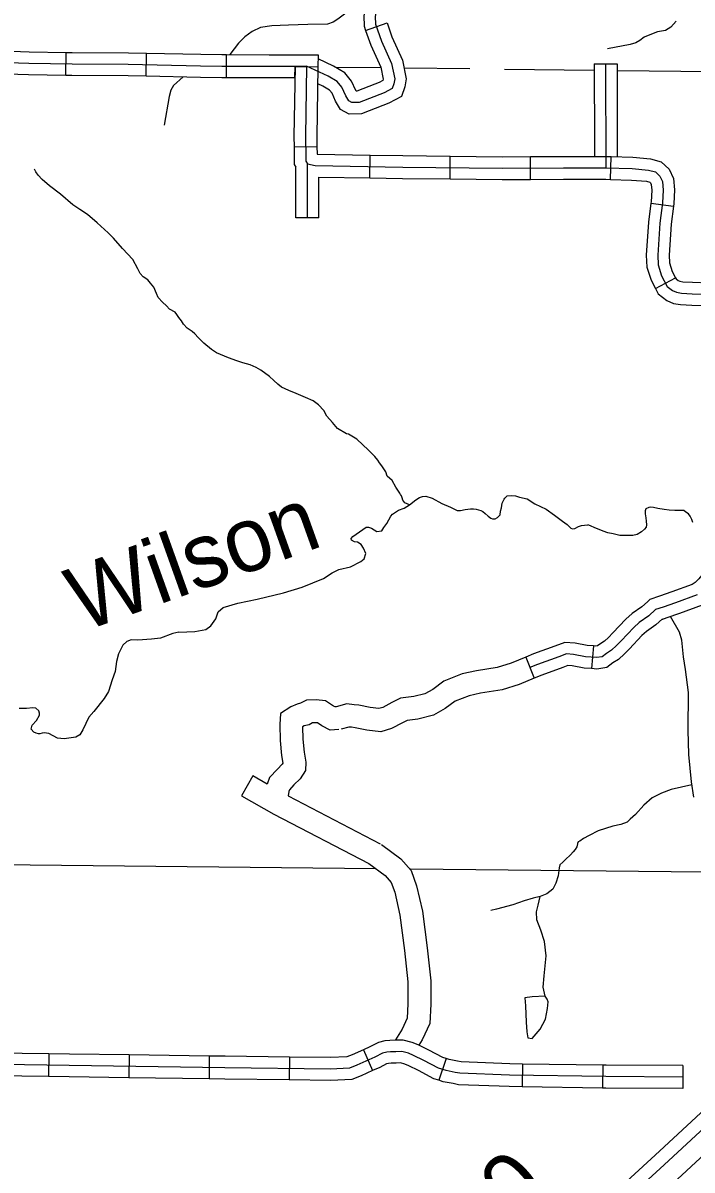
# Model space of a CAD drawing. Extents: x 8749 to 11879, y 13275 to 15339.
# Drawn here: x 9903.6 to 9991.7, y 13618.1 to 13768.9 of the extents above; entities that cross this region are included whole.
import ezdxf

# ---------------------------------------------------------------- set-up
doc = ezdxf.new("R2010")
doc.units = 0
for name, color, linetype in [('Level 19', 7, 'Continuous'), ('Level 31', 7, 'Continuous'), ('Level 32', 7, 'Continuous'), ('Level 35', 7, 'Continuous'), ('Level 45', 7, 'Continuous'), ('Level 46', 7, 'Continuous'), ('Level 48', 7, 'Continuous'), ('Level 5', 7, 'Continuous')]:
    doc.layers.add(name, color=color, linetype=linetype)

msp = doc.modelspace()

# ---------------------------------------------------------------- linework, layer by layer
at = {"layer": 'Level 19'}
for points in [[(9996.99, 13629.44), (9986.85, 13620.03), (9964.99, 13600.02), (9954.18, 13590.48), (9938.87, 13577.88), (9926.88, 13568.51), (9905.66, 13552.12), (9898.16, 13546.32), (9886.51, 13537.43), (9886.51, 13535.29)], [(9886.51, 13535.29), (9899.2, 13544.97), (9906.7, 13550.77), (9927.92, 13567.17), (9939.93, 13576.55), (9955.28, 13589.19), (9966.13, 13598.75), (9988, 13618.78), (9998.09, 13628.1)], [(9999.89, 13626.27), (9989.76, 13616.86), (9967.87, 13596.82), (9956.97, 13587.21), (9941.56, 13574.52), (9929.52, 13565.11), (9908.29, 13548.72), (9900.79, 13542.91), (9886.98, 13532.37)]]:
    msp.add_lwpolyline(points, dxfattribs=at)
at = {"layer": 'Level 31'}
for points in [[(9888.21, 13763.88), (9897.6, 13763.86), (9904.42, 13763.63), (9910.12, 13763.54), (9917.5, 13763.5), (9927.02, 13763.29), (9929.81, 13763.25), (9936.03, 13763.23), (9939.44, 13763.23), (9940.96, 13763.23)], [(9940.96, 13763.23), (9940.81, 13753.97), (9940.85, 13751.33), (9940.85, 13750.74), (9941.07, 13750.41), (9942.09, 13750.16), (9953.63, 13749.97), (9966.7, 13749.83), (9974.76, 13749.86), (9980.36, 13749.86)], [(9980.36, 13749.86), (9983.8, 13749.76), (9985.96, 13749.57), (9986.87, 13749.32), (9987.46, 13748.77), (9987.79, 13748.07), (9987.9, 13746.93), (9987.79, 13745.25), (9987.46, 13742.59), (9987.17, 13738.37), (9987.24, 13737.09), (9987.68, 13735.66), (9988.41, 13734.27), (9989.11, 13733.72), (9989.66, 13733.5), (9990.32, 13733.39), (9991.71, 13733.31), (9993.79, 13733.24), (9996.32, 13733.06), (9998.74, 13732.91), (10002.14, 13732.4), (10004.11, 13732.12)], [(9992.36, 13693.72), (9989.51, 13692.68), (9987.89, 13692.1), (9986.9, 13691.77), (9985.99, 13690.97), (9984.74, 13690.09), (9984.01, 13689.43), (9982.36, 13687.67), (9981.74, 13687.04), (9981.08, 13686.42), (9980.42, 13686.02), (9979.87, 13685.58), (9979.1, 13685.47), (9977.67, 13685.58), (9976.1, 13685.87), (9975.15, 13685.94), (9974.16, 13685.58), (9971.37, 13684.55), (9970.35, 13684.15)]]:
    msp.add_lwpolyline(points, dxfattribs=at)
at = {"layer": 'Level 32'}
for p, q in [((9909.3, 13762.06), (9909.35, 13765.05)), ((9919.85, 13761.95), (9919.92, 13764.95)), ((9930.44, 13761.75), (9930.45, 13764.75)), ((9939.46, 13763.21), (9942.46, 13763.16)), ((9939.33, 13752.61), (9942.33, 13752.65)), ((9949.29, 13748.54), (9949.33, 13751.54)), ((9959.85, 13748.4), (9959.88, 13751.4)), ((9970.43, 13748.34), (9970.42, 13751.34)), ((9980.94, 13748.34), (9981.03, 13751.34)), ((9986.27, 13745.21), (9989.25, 13744.84)), ((9942.57, 13743.3), (9939.57, 13743.3)), ((9986.86, 13733.99), (9989.52, 13735.39)), ((9907.06, 13633.36), (9907.01, 13630.36)), ((9917.61, 13633.21), (9917.57, 13630.21)), ((9928.17, 13633.07), (9928.13, 13630.07)), ((9938.73, 13632.93), (9938.69, 13629.93)), ((9948.44, 13633.89), (9949.66, 13631.15)), ((9959.32, 13632.73), (9958.39, 13629.88)), ((9969.38, 13632.02), (9969.33, 13629.02)), ((9979.93, 13631.86), (9979.89, 13628.86)), ((9990.48, 13631.81), (9990.46, 13628.81))]:
    msp.add_line(p, q, dxfattribs=at)
for points in [[(9898.82, 13765.32), (9904.46, 13765.13), (9909.35, 13765.05)], [(9909.35, 13765.05), (9910.13, 13765.04), (9917.52, 13765), (9919.92, 13764.95)], [(9919.92, 13764.95), (9927.05, 13764.79), (9929.83, 13764.75), (9930.45, 13764.75)], [(9930.45, 13764.75), (9936.03, 13764.73), (9939.44, 13764.73), (9942.49, 13764.73), (9942.46, 13763.16)], [(9898.72, 13762.32), (9904.39, 13762.13), (9909.3, 13762.06)], [(9930.44, 13761.75), (9936.02, 13761.73), (9939.44, 13761.73), (9939.44, 13761.73), (9939.46, 13763.22)], [(9939.46, 13763.21), (9939.31, 13753.97), (9939.33, 13752.61)], [(9942.46, 13763.16), (9942.31, 13753.97), (9942.33, 13752.65)], [(9909.3, 13762.06), (9910.1, 13762.04), (9917.48, 13762), (9919.85, 13761.95)], [(9919.85, 13761.95), (9926.99, 13761.79), (9929.8, 13761.75), (9930.44, 13761.75)], [(9939.33, 13752.61), (9939.35, 13751.32), (9939.35, 13750.29), (9939.57, 13749.96)], [(9942.33, 13752.65), (9942.34, 13751.65), (9949.33, 13751.54)], [(9941.07, 13743.3), (9941.07, 13750.41)], [(9949.33, 13751.54), (9953.65, 13751.47), (9959.88, 13751.4)], [(9959.88, 13751.4), (9966.7, 13751.33), (9970.42, 13751.34)], [(9970.42, 13751.34), (9974.75, 13751.36), (9980.38, 13751.36), (9981.03, 13751.34)], [(9981.03, 13751.34), (9983.88, 13751.26), (9986.23, 13751.06), (9987.63, 13750.66), (9988.69, 13749.67), (9989.26, 13748.48), (9989.4, 13746.96), (9989.28, 13745.11), (9989.25, 13744.84)], [(9939.57, 13743.3), (9939.57, 13749.96)], [(9942.57, 13743.3), (9942.57, 13748.65)], [(9942.57, 13748.65), (9949.29, 13748.54)], [(9949.29, 13748.54), (9953.61, 13748.47), (9959.85, 13748.4)], [(9959.85, 13748.4), (9966.69, 13748.33), (9970.43, 13748.34)], [(9970.43, 13748.34), (9974.76, 13748.36), (9980.34, 13748.36), (9980.94, 13748.34)], [(9980.94, 13748.34), (9983.71, 13748.26), (9985.69, 13748.09), (9986.12, 13747.97), (9986.23, 13747.87), (9986.32, 13747.67), (9986.39, 13746.91), (9986.3, 13745.39), (9986.27, 13745.21)], [(9986.27, 13745.21), (9985.97, 13742.73), (9985.66, 13738.38), (9985.75, 13736.82), (9986.29, 13735.09), (9986.86, 13733.99)], [(9989.25, 13744.84), (9988.95, 13742.44), (9988.67, 13738.36), (9988.73, 13737.36), (9989.07, 13736.23), (9989.52, 13735.39)], [(9989.52, 13735.39), (9989.59, 13735.25), (9989.87, 13735.03), (9990.06, 13734.95), (9990.48, 13734.88), (9991.77, 13734.81), (9993.88, 13734.74), (9996.42, 13734.55), (9998.33, 13734.44)], [(9986.86, 13733.99), (9987.23, 13733.29), (9988.35, 13732.41), (9989.25, 13732.04), (9990.15, 13731.89), (9991.64, 13731.82), (9993.71, 13731.74), (9996.22, 13731.56), (9998.15, 13731.44)], [(9959.32, 13632.73), (9958.9, 13632.87), (9957.06, 13633.83), (9955.66, 13634.53), (9954.85, 13634.86), (9953.68, 13635.17), (9952.69, 13635.14), (9951.91, 13635.12), (9951.28, 13635.07), (9950.44, 13634.87), (9949.31, 13634.28), (9948.44, 13633.89)], [(9907.06, 13633.36), (9896.5, 13633.51)], [(9917.61, 13633.21), (9909.77, 13633.32), (9907.06, 13633.36)], [(9928.17, 13633.07), (9917.61, 13633.21)], [(9938.73, 13632.93), (9930.24, 13633.04), (9928.17, 13633.07)], [(9948.44, 13633.89), (9946.97, 13633.24), (9946.27, 13632.95), (9944.1, 13632.86), (9938.73, 13632.93)], [(9969.38, 13632.02), (9967.71, 13632.05), (9961.3, 13632.29), (9960.83, 13632.39), (9959.72, 13632.6), (9959.32, 13632.73)], [(9949.66, 13631.15), (9948.16, 13630.48), (9946.93, 13629.97), (9944.15, 13629.86), (9938.69, 13629.93)], [(9958.39, 13629.88), (9957.73, 13630.09), (9955.7, 13631.15), (9954.42, 13631.79), (9953.89, 13632.01), (9953.33, 13632.16), (9952.77, 13632.15), (9952.08, 13632.13), (9951.75, 13632.1), (9951.49, 13632.04), (9950.61, 13631.58), (9949.66, 13631.15)], [(9979.93, 13631.86), (9969.38, 13632.02)], [(9990.48, 13631.81), (9980.37, 13631.86), (9979.93, 13631.86)], [(9907.01, 13630.36), (9896.45, 13630.51)], [(9917.57, 13630.21), (9909.73, 13630.32), (9907.01, 13630.36)], [(9928.13, 13630.07), (9917.57, 13630.21)], [(9938.69, 13629.93), (9930.2, 13630.04), (9928.13, 13630.07)], [(9969.33, 13629.02), (9967.63, 13629.05), (9960.95, 13629.3), (9960.25, 13629.44), (9958.96, 13629.69), (9958.39, 13629.88)], [(9979.89, 13628.86), (9969.33, 13629.02)], [(9990.46, 13628.81), (9980.34, 13628.86), (9979.89, 13628.86)]]:
    msp.add_lwpolyline(points, dxfattribs=at)
at = {"layer": 'Level 35'}
for points in [[(9954.54, 13781.4), (9953.79, 13780.32), (9953, 13779.42), (9952.38, 13778.52), (9951.26, 13777.02), (9950.28, 13775.35), (9949.16, 13773.34), (9948.44, 13771.99), (9948.28, 13771.55), (9947.71, 13770.99), (9946.57, 13770.5), (9945.94, 13770.09), (9945.1, 13769.41), (9944.47, 13769), (9943.74, 13768.75), (9941.15, 13768.72), (9938.61, 13768.64), (9936.38, 13768.53), (9934.9, 13768.31), (9933.82, 13767.77)], [(9989.61, 13769.17), (9988.9, 13768.38), (9988.19, 13767.94), (9987.13, 13767.75), (9986.37, 13767.44), (9985.39, 13767.03), (9984.84, 13766.62), (9984.3, 13766.32), (9983.55, 13766.06)], [(9933.82, 13767.77), (9932.84, 13767.08), (9932, 13766.26), (9930.87, 13764.75)], [(9983.55, 13766.06), (9980.55, 13765.5)], [(9924.73, 13761.84), (9923.47, 13760.67), (9923.11, 13760.07), (9922.87, 13759.25), (9922.24, 13755.46)], [(9918.09, 13737.8), (9916.76, 13739.25), (9915.56, 13740.62), (9914.85, 13741.3), (9913.4, 13742.64), (9912.14, 13743.74), (9911.13, 13744.37), (9910.2, 13744.99), (9908.59, 13746.39), (9907.12, 13747.48), (9906.16, 13748.33), (9905.64, 13748.9), (9905.34, 13749.34), (9905.15, 13749.67)], [(9931.77, 13724.47), (9930.71, 13724.86), (9929.64, 13725.3), (9929.1, 13725.55), (9928.44, 13725.96), (9927.46, 13726.81), (9926.69, 13727.54), (9926.28, 13728.04), (9925.93, 13728.34), (9925.27, 13728.77), (9924.76, 13729.32), (9924.51, 13729.76), (9924.15, 13730.2), (9923.91, 13730.58), (9923.66, 13730.88), (9922.93, 13731.26), (9922.52, 13731.7), (9922, 13732.22), (9921.42, 13732.82), (9921.21, 13733.34), (9920.88, 13734.19), (9920.44, 13734.71), (9920.06, 13735.12), (9919.46, 13735.55), (9919.07, 13735.96), (9918.75, 13736.59), (9918.09, 13737.8)], [(9947.58, 13714.2), (9946.49, 13714.84), (9946.24, 13714.9), (9945.04, 13715.61), (9944.36, 13716.37), (9943.65, 13717.22), (9943.24, 13717.96), (9942.53, 13718.7), (9941.85, 13719.22), (9940.81, 13719.65), (9939.58, 13720.17), (9938.62, 13720.58), (9937.69, 13721.02), (9937.18, 13721.4), (9936.66, 13721.92), (9936.11, 13722.44), (9934.94, 13723.26), (9934.34, 13723.59), (9933.54, 13723.95), (9932.56, 13724.22), (9931.77, 13724.47)], [(9954.51, 13705.53), (9953.91, 13705.83), (9953.64, 13706.16), (9953.53, 13706.46), (9953.45, 13706.74), (9953.34, 13706.9), (9953.23, 13707.07), (9952.71, 13707.86), (9952.22, 13708.73), (9951.59, 13709.31), (9951.4, 13709.88), (9950.88, 13710.67), (9950.55, 13711.08), (9950.33, 13711.41), (9949.95, 13711.9), (9949.1, 13712.72), (9947.58, 13714.2)], [(9953.81, 13705.1), (9954.51, 13705.53), (9955.34, 13706.2), (9955.84, 13706.51), (9956.24, 13706.65), (9956.68, 13706.67), (9957.49, 13706.42), (9958.76, 13705.74), (9959.91, 13705.24), (9960.79, 13704.82), (9961.21, 13704.82), (9961.83, 13704.95), (9962.52, 13705.01), (9962.95, 13705.04), (9963.29, 13704.99), (9963.89, 13704.81), (9964.17, 13704.68), (9964.45, 13704.42), (9964.87, 13704.07), (9965.2, 13703.79), (9965.43, 13703.7), (9965.79, 13703.73), (9966.09, 13703.9), (9966.43, 13704.23), (9966.48, 13704.71), (9966.63, 13705.17), (9966.7, 13705.78), (9966.96, 13706.31), (9967.05, 13706.43), (9967.37, 13706.73), (9967.94, 13706.76), (9968.46, 13706.74), (9968.97, 13706.57), (9969.99, 13706.34), (9971, 13705.7), (9972.5, 13704.96), (9973.59, 13704.2), (9974.65, 13703.4), (9975.26, 13702.96), (9975.62, 13702.62), (9975.76, 13702.49), (9975.96, 13702.4), (9976.27, 13702.43), (9976.76, 13702.71), (9977.15, 13702.85), (9977.52, 13702.89), (9977.96, 13702.92)], [(9924.18, 13688.79), (9926.28, 13688.88), (9927.72, 13689.17), (9928.39, 13689.65), (9929.01, 13690.56), (9929.34, 13691.46), (9930.01, 13692.04), (9931.92, 13692.61), (9934.46, 13693.14), (9937.94, 13694), (9940.4, 13694.71), (9943.2, 13695.87), (9944.35, 13696.63), (9945.21, 13697.06), (9946.74, 13697.4), (9948.12, 13698.11), (9948.55, 13698.45), (9948.75, 13699.17), (9948.46, 13699.84), (9948.17, 13700.32), (9947.69, 13700.65), (9947.26, 13700.7), (9946.88, 13700.89), (9946.83, 13701.13), (9947.07, 13701.37), (9948.79, 13702.61), (9949.13, 13702.61), (9949.51, 13702.47), (9950.23, 13702.04), (9950.85, 13702.13), (9951.14, 13702.56), (9951.52, 13703.09), (9952.04, 13704.05), (9952.28, 13704.33), (9953.05, 13704.86), (9953.81, 13705.1)], [(9988.66, 13704.86), (9988.04, 13704.95), (9987.19, 13705.09), (9986.63, 13705.21), (9986.18, 13705.25), (9986.01, 13705.2), (9985.62, 13705.03), (9985.51, 13704.75), (9985.54, 13704.36), (9985.62, 13703.84), (9985.65, 13703.4), (9985.7, 13702.9), (9985.65, 13702.62), (9985.42, 13702.36), (9985.03, 13702.01), (9984.46, 13701.65), (9983.9, 13701.51), (9983.06, 13701.51), (9982.2, 13701.53), (9981.31, 13701.75), (9980.62, 13701.89), (9979.98, 13702.11), (9979.47, 13702.29), (9978.91, 13702.53), (9978.33, 13702.79), (9977.96, 13702.92)], [(9991.79, 13703.24), (9991.64, 13703.64), (9991.46, 13704.07), (9991.23, 13704.35), (9990.89, 13704.59), (9990.59, 13704.79), (9990.15, 13704.82), (9989.44, 13704.82), (9988.66, 13704.86)], [(9924.18, 13688.79), (9923.39, 13688.62), (9921.75, 13688.02), (9920.55, 13687.88), (9918.75, 13687.77), (9917.87, 13687.8), (9917.3, 13687.58), (9916.81, 13687.12), (9916.21, 13685.97), (9915.96, 13684.96), (9915.8, 13683.65), (9915.39, 13682.53), (9914.9, 13681), (9914.32, 13680.07), (9912.96, 13678.37)], [(9906.46, 13675.59), (9906.16, 13675.51), (9905.89, 13675.43), (9905.7, 13675.43), (9905.37, 13675.51), (9905.07, 13675.65), (9904.74, 13676.06), (9904.85, 13676.6), (9905.43, 13677.18), (9905.84, 13677.89), (9905.84, 13678.16), (9905.73, 13678.46), (9905.34, 13678.82), (9904.94, 13678.87), (9904.12, 13678.79), (9903.13, 13678.76)], [(9912.96, 13678.37), (9912.31, 13677.62), (9911.93, 13676.8), (9911.54, 13675.95), (9911.13, 13675.32), (9910.59, 13674.99), (9909.09, 13674.77), (9908.19, 13674.86), (9907.04, 13675.48), (9906.46, 13675.59)], [(9988.94, 13668.11), (9987.67, 13667.64), (9986.44, 13667.01), (9985.33, 13666.08), (9984.24, 13664.85), (9983.55, 13664.2), (9983.14, 13663.84), (9982.3, 13663.52), (9981.26, 13663.3), (9979.33, 13662.7), (9978.13, 13662.07), (9977.42, 13661.66), (9976.93, 13661.33), (9976.71, 13661.22), (9976.63, 13661.03), (9976.58, 13660.71), (9976.52, 13660.57), (9976.33, 13660.21), (9976.06, 13659.91), (9975.68, 13659.53), (9975.05, 13658.9), (9974.7, 13658.55), (9974.31, 13658.2), (9974.2, 13657.81), (9974.07, 13656.78)], [(9991.66, 13668.74), (9988.94, 13668.11)], [(9974.07, 13656.78), (9973.77, 13655.81), (9973.38, 13655.02), (9972.59, 13654.42), (9971.69, 13654.04), (9970.79, 13653.85), (9969.62, 13653.5), (9968.1, 13652.95), (9965.97, 13652.4), (9965.23, 13652.21)], [(9972.36, 13640.94), (9972.08, 13642.12), (9972.22, 13643.63), (9972.5, 13646.23), (9972.27, 13648.12), (9971.79, 13649.63), (9971.27, 13651), (9971.23, 13652.04), (9971.42, 13652.89), (9971.69, 13654.04)], [(9972.36, 13640.94), (9970.66, 13640.85), (9969.67, 13640.71), (9969.77, 13639.67), (9969.86, 13637.54), (9969.95, 13636.27), (9970.1, 13635.46), (9970.66, 13635.37), (9971.7, 13636.6), (9972.41, 13637.92), (9972.69, 13639.34), (9972.74, 13640.19), (9972.61, 13640.57), (9972.36, 13640.94)]]:
    msp.add_lwpolyline(points, dxfattribs=at)
at = {"layer": 'Level 45'}
for p, q in [((9948.74, 13767.94), (9951.58, 13768.92)), ((9978.82, 13763.55), (9981.82, 13763.56)), ((9978.72, 13687), (9978.48, 13684.01))]:
    msp.add_line(p, q, dxfattribs=at)
for points in [[(9955.02, 13777.77), (9953.87, 13777.56), (9952.36, 13777.04), (9950.86, 13775.89), (9949.88, 13774.38), (9948.88, 13771.95), (9948.5, 13769.87), (9948.55, 13768.49), (9948.74, 13767.94)], [(9954.25, 13776.1), (9953.08, 13775.7), (9951.98, 13774.86), (9951.21, 13773.68), (9950.33, 13771.52), (9950, 13769.76), (9950.04, 13768.77), (9950.81, 13766.54), (9952.16, 13763.57), (9952.56, 13761.55), (9952.46, 13760.89), (9952.24, 13760.3), (9951.17, 13759.72), (9947.88, 13758.47), (9946.93, 13758.44), (9946.52, 13758.66), (9946.12, 13759.31), (9945.61, 13760.45), (9944.99, 13761.22), (9943.81, 13761.92), (9940.96, 13763.23)], [(9951.58, 13768.92), (9952.2, 13767.09), (9953.6, 13764.03), (9954.09, 13761.58), (9953.91, 13760.5), (9953.45, 13759.26), (9951.8, 13758.35), (9951.02, 13758.06)], [(9948.74, 13767.94), (9949.41, 13765.98), (9950.73, 13763.1), (9951.04, 13761.53), (9951.01, 13761.34), (9950.54, 13761.08), (9949.96, 13760.86)], [(9949.96, 13760.86), (9947.58, 13759.96), (9947.49, 13759.96), (9947.45, 13760.02), (9946.9, 13761.24), (9945.98, 13762.37), (9944.51, 13763.25), (9942.48, 13764.18)], [(9978.82, 13763.55), (9978.85, 13752.99)], [(9980.32, 13763.56), (9980.36, 13749.86)], [(9981.82, 13763.56), (9981.85, 13753)], [(9951.02, 13758.06), (9948.18, 13756.98), (9946.57, 13756.92), (9945.45, 13757.53), (9944.79, 13758.61), (9944.32, 13759.66), (9943.99, 13760.07), (9943.11, 13760.59), (9942.43, 13760.9)], [(9978.85, 13752.99), (9978.85, 13751.36)], [(9981.85, 13753), (9981.85, 13751.32)], [(9994.36, 13698.08), (9993.81, 13697.46), (9993.17, 13696.52), (9992.6, 13695.82), (9992.11, 13695.33), (9991.7, 13695.07), (9989.01, 13694.1), (9987.4, 13693.52), (9986.14, 13693.1), (9985.82, 13692.81)], [(9996.61, 13696.1), (9996.19, 13695.62), (9995.58, 13694.72), (9994.83, 13693.81), (9994, 13692.98), (9993.03, 13692.36), (9990.02, 13691.27), (9988.38, 13690.68), (9987.67, 13690.45), (9987.8, 13690.56)], [(9985.82, 13692.81), (9985.06, 13692.14), (9983.8, 13691.26), (9982.96, 13690.5), (9981.28, 13688.71), (9980.69, 13688.12), (9980.16, 13687.62), (9979.56, 13687.25), (9979.25, 13687), (9979.05, 13686.97), (9978.72, 13687)], [(9987.8, 13690.56), (9986.92, 13689.79), (9985.68, 13688.91), (9985.06, 13688.35), (9983.44, 13686.62), (9982.79, 13685.97), (9982, 13685.22), (9981.28, 13684.79), (9980.49, 13684.15), (9979.15, 13683.96), (9978.48, 13684.01)], [(9978.72, 13687), (9977.87, 13687.07), (9976.29, 13687.36), (9974.93, 13687.46), (9973.64, 13686.98), (9970.84, 13685.95), (9969.8, 13685.54), (9970.9, 13682.75)], [(9978.48, 13684.01), (9977.48, 13684.09), (9975.9, 13684.38), (9975.36, 13684.42), (9974.68, 13684.17), (9971.91, 13683.15), (9970.9, 13682.75)], [(9961.12, 13630.8), (9960.54, 13630.91), (9959.34, 13631.15), (9958.31, 13631.48), (9956.38, 13632.49), (9955.04, 13633.16), (9954.37, 13633.43), (9953.51, 13633.67), (9952.73, 13633.64), (9951.99, 13633.62), (9951.51, 13633.58), (9950.97, 13633.46), (9949.96, 13632.93), (9947.57, 13631.86), (9946.6, 13631.46), (9944.12, 13631.36)], [(9944.12, 13631.36), (9930.22, 13631.54), (9909.75, 13631.82), (9886.15, 13632.16)], [(9990.47, 13630.31), (9980.36, 13630.36), (9967.67, 13630.55), (9961.12, 13630.8)]]:
    msp.add_lwpolyline(points, dxfattribs=at)
at = {"layer": 'Level 46'}
for points in [[(9991.91, 13667.12), (9991.62, 13669.13), (9991.26, 13672.72), (9991.2, 13675.93), (9991.22, 13680.87), (9990.83, 13683.89), (9990.58, 13685.56), (9990.34, 13687.77), (9990.05, 13688.82), (9988.85, 13690.85)], [(9969.8, 13685.54), (9967.91, 13684.73), (9966.03, 13684.16), (9963.31, 13683.73), (9961.46, 13683.33), (9959.04, 13682.37), (9957.56, 13681.28), (9956.54, 13680.69), (9955.07, 13680.33), (9953.33, 13680.12), (9952.2, 13679.56), (9951, 13678.92), (9950.48, 13678.76), (9949.35, 13678.9), (9947.86, 13679.19), (9947.25, 13679.27), (9946.28, 13679.38), (9944.88, 13678.98)], [(9970.9, 13682.75), (9968.94, 13681.91), (9966.71, 13681.23), (9963.86, 13680.78), (9962.34, 13680.45), (9960.51, 13679.73), (9959.21, 13678.76), (9957.67, 13677.88), (9955.61, 13677.37), (9954.21, 13677.21), (9953.58, 13676.89), (9952.15, 13676.14), (9950.76, 13675.71), (9948.88, 13675.94), (9947.37, 13676.23), (9946.88, 13676.3), (9946.54, 13676.33), (9945.54, 13676.05)], [(9944.88, 13678.98), (9944.72, 13678.97), (9944.5, 13679.08), (9943.47, 13679.79), (9942.25, 13679.91), (9940.96, 13679.86), (9940.19, 13679.45), (9939.71, 13679.32), (9938.88, 13678.98), (9937.53, 13678.13), (9937.44, 13676.68), (9937.48, 13674.58), (9937.68, 13672.59), (9937.86, 13671.58), (9937.77, 13671.44), (9937.13, 13670.79), (9936.11, 13669.68), (9935.78, 13668.84)], [(9945.2, 13675.99), (9944.08, 13675.94), (9942.98, 13676.49), (9942.41, 13676.88), (9942.16, 13676.9), (9941.76, 13676.89), (9941.29, 13676.64), (9940.67, 13676.47), (9940.45, 13676.38), (9940.48, 13674.76), (9940.65, 13673.01), (9940.89, 13671.71), (9940.81, 13670.62), (9940.12, 13669.54), (9939.29, 13668.72), (9938.7, 13668.07), (9938.62, 13667.86), (9938.56, 13667.28)], [(9933.9, 13669.9), (9932.42, 13667.29), (9936.68, 13664.87), (9949.16, 13658.38)], [(9935.78, 13668.84), (9933.9, 13669.9)], [(9938.56, 13667.28), (9950.65, 13660.99)], [(9950.84, 13660.87), (9953.39, 13659.02), (9954.71, 13657.45), (9955.45, 13655.46), (9956.2, 13652.13), (9956.82, 13647.32), (9957.3, 13642.98), (9957.3, 13639.89), (9957.2, 13637.33), (9956.18, 13635.2), (9955.75, 13634.48)], [(9949.16, 13658.38), (9951.33, 13656.8), (9952.08, 13655.91), (9952.57, 13654.6), (9953.24, 13651.61), (9953.84, 13646.97), (9954.3, 13642.81), (9954.3, 13639.95), (9954.22, 13638.07), (9953.54, 13636.62), (9952.67, 13635.19)]]:
    msp.add_lwpolyline(points, dxfattribs=at)
at = {"layer": 'Level 5'}
for points in [[(9950.77, 13763), (9944.8, 13763.07)], [(9962.45, 13762.86), (9953.81, 13762.97)], [(9978.82, 13762.66), (9967, 13762.81)], [(9994.42, 13762.48), (9981.82, 13762.63)], [(9950.09, 13657.7), (9888.02, 13658.36)], [(9993.25, 13657.24), (9954.64, 13657.65)]]:
    msp.add_lwpolyline(points, dxfattribs=at)

# ---------------------------------------------------------------- texts
at = {"layer": 'Level 35'}
msp.add_text('Wilson', height=8.448, rotation=19.7057, dxfattribs=at).set_placement((9911.42, 13688.79))
at = {"layer": 'Level 48'}
msp.add_text('7.0', height=8.448, rotation=41.5595, dxfattribs=at).set_placement((9961.48, 13604.62))

doc.saveas('drawing.dxf')
